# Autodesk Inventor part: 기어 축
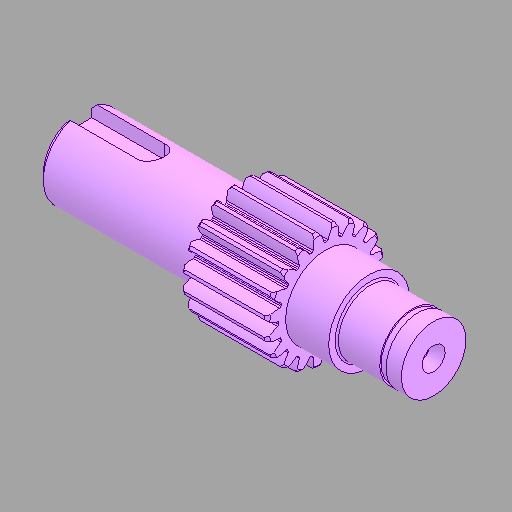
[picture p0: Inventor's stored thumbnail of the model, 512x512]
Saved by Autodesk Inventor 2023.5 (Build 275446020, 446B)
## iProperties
Created: 2026-03
Part Number: 기어 축
Material: 강철, 합금
Document SubType Name: Modeling
Designer: mirae
Density: 7.73 g/cm^3
Appearance: 기본값
Author: jhkim
Sending System: Autodesk Inventor 2026
Preprocessor: ST-DEVELOPER v20.1
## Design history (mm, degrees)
node "기어 축1"
node "솔리드2"
node "솔리드1"
